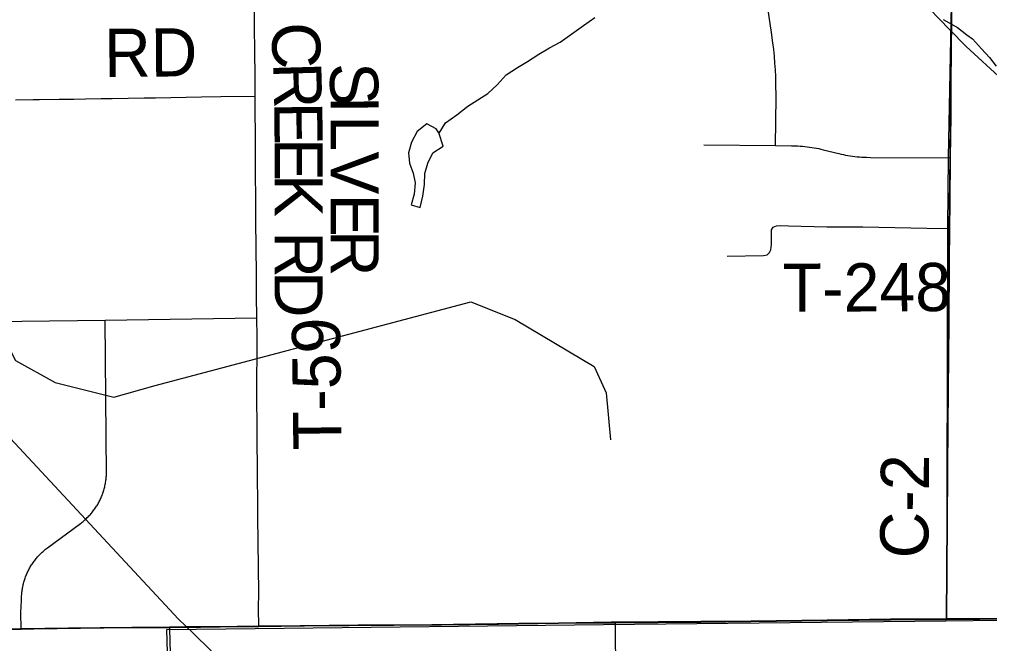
# Model space of a CAD drawing. Extents: x 0 to 34, y -5 to 22.
# Drawn here: x 2.904 to 4.048, y 16.518 to 17.254 of the extents above; entities that cross this region are included whole.
import ezdxf

# ---------------------------------------------------------------- set-up
doc = ezdxf.new("R2010")
doc.units = 0
for name, color, linetype in [('GM_X_County_Road', 7, 'Continuous'), ('GM_X_County_Road_Text', 7, 'Continuous'), ('GM_X_Minor_Lake', 7, 'Continuous'), ('GM_X_Minor_River', 7, 'Continuous'), ('GM_X_Rail_Line', 7, 'Continuous'), ('GM_X_Section', 7, 'Continuous'), ('GM_X_Township_Road', 7, 'Continuous'), ('GM_X_Township_Road_Text', 7, 'Continuous'), ('GM_X_US_Route', 7, 'Continuous'), ('SC_Scratch2', 7, 'Continuous'), ('SH_Cut_Line', 7, 'Continuous')]:
    doc.layers.add(name, color=color, linetype=linetype)

msp = doc.modelspace()

# ---------------------------------------------------------------- linework, layer by layer
at = {"layer": 'GM_X_County_Road'}
msp.add_line((3.0678, 16.5373), (3.0817, 16.5373), dxfattribs=at)
for points in [[(4.0021, 17.0911), (4.0028, 17.1406), (4.0029, 17.1826), (4.003, 17.1952), (4.0036, 17.2488), (4.0037, 17.2604), (4.0038, 17.3788), (4.0038, 17.3907)], [(4.0015, 17.0078), (4.0017, 17.0387), (4.0021, 17.0911)], [(3.9974, 16.5469), (3.9977, 16.5831), (3.9985, 16.6758), (3.9987, 16.6957), (4.0007, 16.8971), (4.0011, 16.9678), (4.0015, 17.0078)], [(3.1866, 16.5386), (3.2406, 16.5393), (3.346, 16.5402), (3.402, 16.5406), (3.4691, 16.5413), (3.5392, 16.5424), (3.6072, 16.543)], [(3.6072, 16.543), (3.7078, 16.5438), (3.7669, 16.5444), (3.8569, 16.5455), (3.9315, 16.5464), (3.9873, 16.5467), (3.9974, 16.5469)], [(3.6106, 16.2489), (3.6102, 16.2742), (3.6099, 16.2866), (3.6098, 16.2985), (3.6097, 16.3108), (3.6092, 16.3377), (3.6088, 16.366), (3.6084, 16.3982), (3.6081, 16.4228), (3.6078, 16.4524), (3.6077, 16.4706), (3.6075, 16.498), (3.6073, 16.5248), (3.6072, 16.543)], [(3.9974, 16.5469), (4.0759, 16.5475), (4.1294, 16.5476)], [(2.5827, 16.5315), (2.6019, 16.5317), (2.7086, 16.5327), (2.7705, 16.5335), (2.8341, 16.5343), (2.8621, 16.5347), (2.9065, 16.5353)], [(2.9065, 16.5353), (2.9213, 16.5357), (3.0041, 16.5369), (3.0469, 16.5373), (3.0678, 16.5373)], [(3.0817, 16.5373), (3.1179, 16.5378), (3.1646, 16.5384), (3.1866, 16.5386)]]:
    msp.add_lwpolyline(points, dxfattribs=at)
at = {"layer": 'GM_X_Minor_Lake'}
for points in [[(3.3989, 17.1203), (3.3957, 17.1252), (3.3846, 17.1312), (3.3733, 17.1219), (3.3666, 17.1093), (3.3633, 17.0967), (3.3642, 17.0846), (3.3685, 17.0728), (3.3709, 17.0614), (3.3699, 17.0481), (3.3662, 17.0355), (3.3768, 17.0326)], [(3.3992, 17.1199), (3.3957, 17.1252), (3.3846, 17.1312), (3.3733, 17.1219), (3.3666, 17.1093), (3.3633, 17.0967), (3.3642, 17.0846), (3.3685, 17.0728), (3.3709, 17.0614), (3.3699, 17.0481), (3.3662, 17.0355), (3.3768, 17.0326)], [(3.3768, 17.0326), (3.3802, 17.0459), (3.3819, 17.0596), (3.3822, 17.0726), (3.3858, 17.0848), (3.3918, 17.097), (3.4039, 17.1047), (3.3989, 17.1203)], [(3.3768, 17.0326), (3.3802, 17.0459), (3.3819, 17.0596), (3.3822, 17.0726), (3.3858, 17.0848), (3.3918, 17.097), (3.4039, 17.1047), (3.3989, 17.1203)]]:
    msp.add_lwpolyline(points, dxfattribs=at)
at = {"layer": 'GM_X_Minor_River'}
for points in [[(3.3992, 17.1199), (3.4066, 17.1321), (3.4202, 17.1418), (3.433, 17.1518), (3.4447, 17.1595), (3.4568, 17.1669), (3.4677, 17.1769), (3.4783, 17.1888), (3.4915, 17.1973), (3.5036, 17.2046), (3.5168, 17.2131), (3.5292, 17.2205), (3.5421, 17.2275), (3.5557, 17.2371), (3.5696, 17.2468), (3.5828, 17.2564)], [(3.9934, 17.2541), (4.0104, 17.2445), (4.0215, 17.2358), (4.028, 17.2313), (4.0387, 17.2196), (4.0479, 17.2094), (4.056, 17.1989)]]:
    msp.add_lwpolyline(points, dxfattribs=at)
at = {"layer": 'GM_X_Rail_Line'}
for points in [[(4.0009, 17.2424), (3.9071, 17.3398), (3.6464, 17.5481), (3.5412, 17.6511), (3.4669, 17.7587), (3.3766, 17.8423), (3.2794, 17.8961), (3.0993, 17.9799), (2.9896, 18.0297), (2.9372, 18.0489)], [(4.0009, 17.2424), (4.0204, 17.2221), (4.0632, 17.1829), (4.0857, 17.1437), (4.1676, 16.9857), (4.2865, 16.5727), (4.2939, 16.5478)], [(2.7755, 17.0929), (2.7839, 16.8938), (2.8047, 16.8556), (3.092, 16.5471), (3.1083, 16.5313)], [(2.7755, 17.0929), (2.829, 16.9821), (2.8445, 16.9579), (2.8999, 16.8522), (2.9467, 16.8261), (3.0159, 16.8088), (3.0644, 16.8226), (3.4368, 16.9213), (3.4887, 16.9005), (3.5822, 16.845), (3.5961, 16.8138), (3.6012, 16.7584)], [(3.1083, 16.5313), (3.1544, 16.4864), (3.1977, 16.4708), (3.357, 16.469), (3.3985, 16.4621), (3.4297, 16.4153)]]:
    msp.add_lwpolyline(points, dxfattribs=at)
at = {"layer": 'GM_X_Section'}
msp.add_lwpolyline([(4.1248, 16.5469), (4.1342, 15.5936), (3.6228, 15.592), (3.1044, 15.6177), (3.0783, 16.5351), (3.1825, 16.5361), (3.5929, 16.5408), (3.9967, 16.5453)], close=True, dxfattribs=at)
at = {"layer": 'GM_X_Township_Road'}
for points in [[(3.1823, 17.1638), (3.1822, 17.1886), (3.1818, 17.2155), (3.1815, 17.2463), (3.1814, 17.2576), (3.1812, 17.275), (3.1808, 17.303), (3.1808, 17.3098), (3.1805, 17.3314), (3.1802, 17.358), (3.1799, 17.3885)], [(3.7958, 17.1055), (3.7964, 17.1626), (3.7963, 17.1786), (3.796, 17.1867), (3.7956, 17.1947), (3.7951, 17.2027), (3.7945, 17.2107), (3.7937, 17.2187), (3.7928, 17.2267), (3.7911, 17.2387), (3.7854, 17.2755), (3.7844, 17.2823), (3.784, 17.286), (3.7836, 17.2897), (3.7833, 17.2934), (3.7831, 17.2971), (3.7829, 17.3008), (3.7828, 17.3045), (3.7817, 17.3905)], [(2.8998, 17.1593), (2.9205, 17.1596), (2.9282, 17.1597), (2.9514, 17.1601), (2.9684, 17.1603), (2.9824, 17.1605), (3.0009, 17.1608), (3.0139, 17.161), (3.0517, 17.1616), (3.0648, 17.1619), (3.1189, 17.1628), (3.1417, 17.1631), (3.1823, 17.1638)], [(3.1866, 16.5386), (3.1861, 16.5603), (3.1865, 16.5782), (3.1857, 16.6682), (3.1856, 16.6795), (3.1853, 16.7206), (3.1849, 16.7617), (3.1848, 16.7726), (3.1843, 16.8096), (3.1846, 16.8795), (3.1843, 16.9022), (3.1841, 16.9286), (3.1838, 16.9523), (3.1834, 16.9864), (3.1832, 17.0151), (3.1831, 17.0435), (3.1829, 17.0719), (3.1827, 17.1003), (3.1823, 17.1638)], [(3.7111, 17.1065), (3.7958, 17.1055), (3.8148, 17.1053), (3.8194, 17.1052), (3.8221, 17.1051), (3.8249, 17.1049), (3.8276, 17.1047), (3.8304, 17.1044), (3.8331, 17.1041), (3.8358, 17.1037), (3.8386, 17.1033), (3.8413, 17.1029), (3.844, 17.1024), (3.8467, 17.1018), (3.8494, 17.1012), (3.8521, 17.1006), (3.8704, 17.096), (3.8731, 17.0954), (3.8758, 17.0948), (3.8785, 17.0943), (3.8812, 17.0938), (3.8839, 17.0933), (3.8866, 17.0929), (3.8894, 17.0926), (3.8921, 17.0923), (3.8948, 17.092), (3.8976, 17.0918), (3.9003, 17.0917), (3.9031, 17.0916), (3.9076, 17.0915), (4.0021, 17.0911)], [(3.7389, 16.975), (3.7818, 16.9758), (3.7858, 16.9766), (3.7888, 16.9792), (3.7903, 16.9825), (3.791, 16.989), (3.7912, 17.0063), (3.7931, 17.0091), (3.7969, 17.0107), (3.8021, 17.0112), (3.8112, 17.011), (3.8562, 17.0098), (3.8986, 17.0095), (3.9743, 17.008), (4.0015, 17.0078)], [(2.8414, 16.8975), (3.0057, 16.8998), (3.1843, 16.9022)], [(2.9065, 16.5353), (2.9061, 16.5551), (2.9069, 16.569), (2.907, 16.5748), (2.9071, 16.5762), (2.9072, 16.5775), (2.9074, 16.5789), (2.9075, 16.5802), (2.9077, 16.5816), (2.9079, 16.5829), (2.9081, 16.5842), (2.9084, 16.5855), (2.9087, 16.5868), (2.909, 16.5881), (2.9093, 16.5894), (2.9096, 16.5907), (2.91, 16.5919), (2.9104, 16.5932), (2.9108, 16.5944), (2.9112, 16.5957), (2.9117, 16.5969), (2.9121, 16.5982), (2.9126, 16.5994), (2.9131, 16.6006), (2.9137, 16.6018), (2.9142, 16.603), (2.9148, 16.6042), (2.9154, 16.6054), (2.916, 16.6066), (2.9167, 16.6077), (2.9173, 16.6089), (2.918, 16.61), (2.9187, 16.6111), (2.9194, 16.6122), (2.9201, 16.6133), (2.9209, 16.6144), (2.9217, 16.6155), (2.9225, 16.6165), (2.9233, 16.6175), (2.9241, 16.6186), (2.9249, 16.6196), (2.9258, 16.6206), (2.9267, 16.6215), (2.9276, 16.6225), (2.9285, 16.6235), (2.9294, 16.6244), (2.9304, 16.6253), (2.9313, 16.6262), (2.9323, 16.6271), (2.9333, 16.6279), (2.9343, 16.6288), (2.9353, 16.6296), (2.9364, 16.6304), (2.9374, 16.6312), (2.9765, 16.6601), (2.9775, 16.6608), (2.9786, 16.6617), (2.9796, 16.6625), (2.9806, 16.6633), (2.9816, 16.6642), (2.9826, 16.6651), (2.9835, 16.666), (2.9845, 16.6669), (2.9854, 16.6678), (2.9863, 16.6688), (2.9873, 16.6697), (2.9881, 16.6707), (2.989, 16.6717), (2.9898, 16.6727), (2.9907, 16.6738), (2.9915, 16.6748), (2.9923, 16.6759), (2.9931, 16.6769), (2.9938, 16.678), (2.9946, 16.6791), (2.9953, 16.6802), (2.996, 16.6813), (2.9967, 16.6825), (2.9973, 16.6836), (2.998, 16.6848), (2.9986, 16.6859), (2.9992, 16.6871), (2.9998, 16.6883), (3.0003, 16.6895), (3.0008, 16.6907), (3.0014, 16.6919), (3.0019, 16.6931), (3.0023, 16.6944), (3.0028, 16.6956), (3.0032, 16.6969), (3.0036, 16.6981), (3.004, 16.6994), (3.0044, 16.7007), (3.0047, 16.7019), (3.005, 16.7032), (3.0053, 16.7045), (3.0056, 16.7058), (3.0058, 16.7071), (3.0061, 16.7084), (3.0063, 16.7097), (3.0065, 16.711), (3.0066, 16.7123), (3.0068, 16.7137), (3.0069, 16.715), (3.007, 16.7163), (3.007, 16.7176), (3.0057, 16.8998)], [(3.1042, 15.7751), (3.1029, 15.8055), (3.1014, 15.8584), (3.0997, 15.9112), (3.0987, 15.9391), (3.0958, 16.0196), (3.0932, 16.0816), (3.0915, 16.1469), (3.0896, 16.2555), (3.089, 16.2772), (3.0883, 16.3048), (3.0878, 16.3248), (3.0873, 16.3562), (3.0865, 16.381), (3.0854, 16.4089), (3.0839, 16.4553), (3.0826, 16.5049), (3.082, 16.5233), (3.0817, 16.534), (3.0817, 16.5373)]]:
    msp.add_lwpolyline(points, dxfattribs=at)
at = {"layer": 'GM_X_US_Route'}
for points in [[(4.0095, 18.3868), (4.0056, 17.7327), (4.0045, 17.6221), (4.0045, 17.3912), (4.0018, 17.0912), (4.0007, 17.009), (3.9972, 16.5475), (4.0757, 16.548)], [(2.8659, 16.535), (2.9062, 16.5357), (2.9622, 16.5366), (3.0368, 16.5375), (3.0815, 16.5379), (3.102, 16.5381), (3.161, 16.5386), (3.1859, 16.5389), (3.2355, 16.5395), (3.3038, 16.5402), (3.3908, 16.5406), (3.4933, 16.5419), (3.5398, 16.5426), (3.602, 16.5435), (3.607, 16.5435), (3.7076, 16.5444), (3.7667, 16.545), (3.8567, 16.546), (3.9313, 16.547), (3.9871, 16.5473), (3.9972, 16.5475), (4.0007, 17.009), (4.0018, 17.0912), (4.0045, 17.3912)], [(4.0757, 16.548), (3.9972, 16.5475), (3.9871, 16.5473), (3.9313, 16.547), (3.8567, 16.546), (3.7667, 16.545), (3.7076, 16.5444), (3.607, 16.5435), (3.602, 16.5435), (3.5398, 16.5426), (3.4933, 16.5419), (3.3908, 16.5406), (3.3038, 16.5402), (3.2355, 16.5395), (3.1859, 16.5389), (3.161, 16.5386), (3.102, 16.5381), (3.0815, 16.5379), (3.0368, 16.5375), (2.9622, 16.5366), (2.9062, 16.5357), (2.8659, 16.535)]]:
    msp.add_lwpolyline(points, dxfattribs=at)
at = {"layer": 'SC_Scratch2'}
msp.add_lwpolyline([(4.0088, 19.1096), (4.0056, 17.7327), (4.0058, 17.6217), (4.0052, 17.3913), (3.9994, 17.0916), (3.9984, 17.0094), (3.9972, 16.5475), (4.0757, 16.548)], dxfattribs=at)
at = {"layer": 'SH_Cut_Line'}
for points in [[(4.0095, 18.3868), (4.0056, 17.7327), (4.0045, 17.6221), (4.0045, 17.3912), (4.0018, 17.0912), (4.0007, 17.009), (3.9972, 16.5475), (4.0757, 16.548)], [(2.8659, 16.535), (2.9062, 16.5357), (2.9622, 16.5366), (3.0368, 16.5375), (3.0815, 16.5379), (3.102, 16.5381), (3.161, 16.5386), (3.1859, 16.5389), (3.2355, 16.5395), (3.3038, 16.5402), (3.3908, 16.5406), (3.4933, 16.5419), (3.5398, 16.5426), (3.602, 16.5435), (3.607, 16.5435), (3.7076, 16.5444), (3.7667, 16.545), (3.8567, 16.546), (3.9313, 16.547), (3.9871, 16.5473), (3.9972, 16.5475), (4.0007, 17.009), (4.0018, 17.0912), (4.0045, 17.3912)], [(4.0757, 16.548), (3.9972, 16.5475), (3.9871, 16.5473), (3.9313, 16.547), (3.8567, 16.546), (3.7667, 16.545), (3.7076, 16.5444), (3.607, 16.5435), (3.602, 16.5435), (3.5398, 16.5426), (3.4933, 16.5419), (3.3908, 16.5406), (3.3038, 16.5402), (3.2355, 16.5395), (3.1859, 16.5389), (3.161, 16.5386), (3.102, 16.5381), (3.0815, 16.5379), (3.0368, 16.5375), (2.9622, 16.5366), (2.9062, 16.5357), (2.8659, 16.535)]]:
    msp.add_lwpolyline(points, dxfattribs=at)

# ---------------------------------------------------------------- texts
at = {"layer": 'GM_X_County_Road_Text'}
msp.add_text('C-2', height=0.05682, rotation=89.4574, dxfattribs=at).set_placement((3.9758, 16.6187))
at = {"layer": 'GM_X_Township_Road_Text'}
for s, height, rotation, p in [('RD', 0.05682, 0.4936, (3.0046, 17.1862)), ('C', 0.0568, 272.7488, (3.2011, 17.2494)), ('R', 0.0568, 271.6239, (3.2034, 17.2031)), ('S', 0.0568, 272.4334, (3.2696, 17.202)), ('I', 0.0568, 270.1327, (3.2712, 17.1643)), ('E', 0.0568, 270.6429, (3.2047, 17.1567)), ('L', 0.0568, 270, (3.2713, 17.141)), ('E', 0.0568, 270.0771, (3.2052, 17.1144)), ('V', 0.0568, 269.9981, (3.2713, 17.0986)), ('K', 0.0568, 270, (3.2052, 17.0719)), ('E', 0.0568, 269.9985, (3.2713, 17.0485)), ('R', 0.0568, 269.9991, (3.2052, 17.0044)), ('R', 0.0568, 269.9991, (3.2713, 17.006)), ('T-248', 0.05682, 0.2807, (3.8044, 16.9094)), ('D', 0.0568, 270, (3.2052, 16.9577)), ('T-59', 0.05682, 90.7083, (3.2842, 16.7467))]:
    msp.add_text(s, height=height, rotation=rotation, dxfattribs=at).set_placement(p)

doc.saveas('drawing.dxf')
